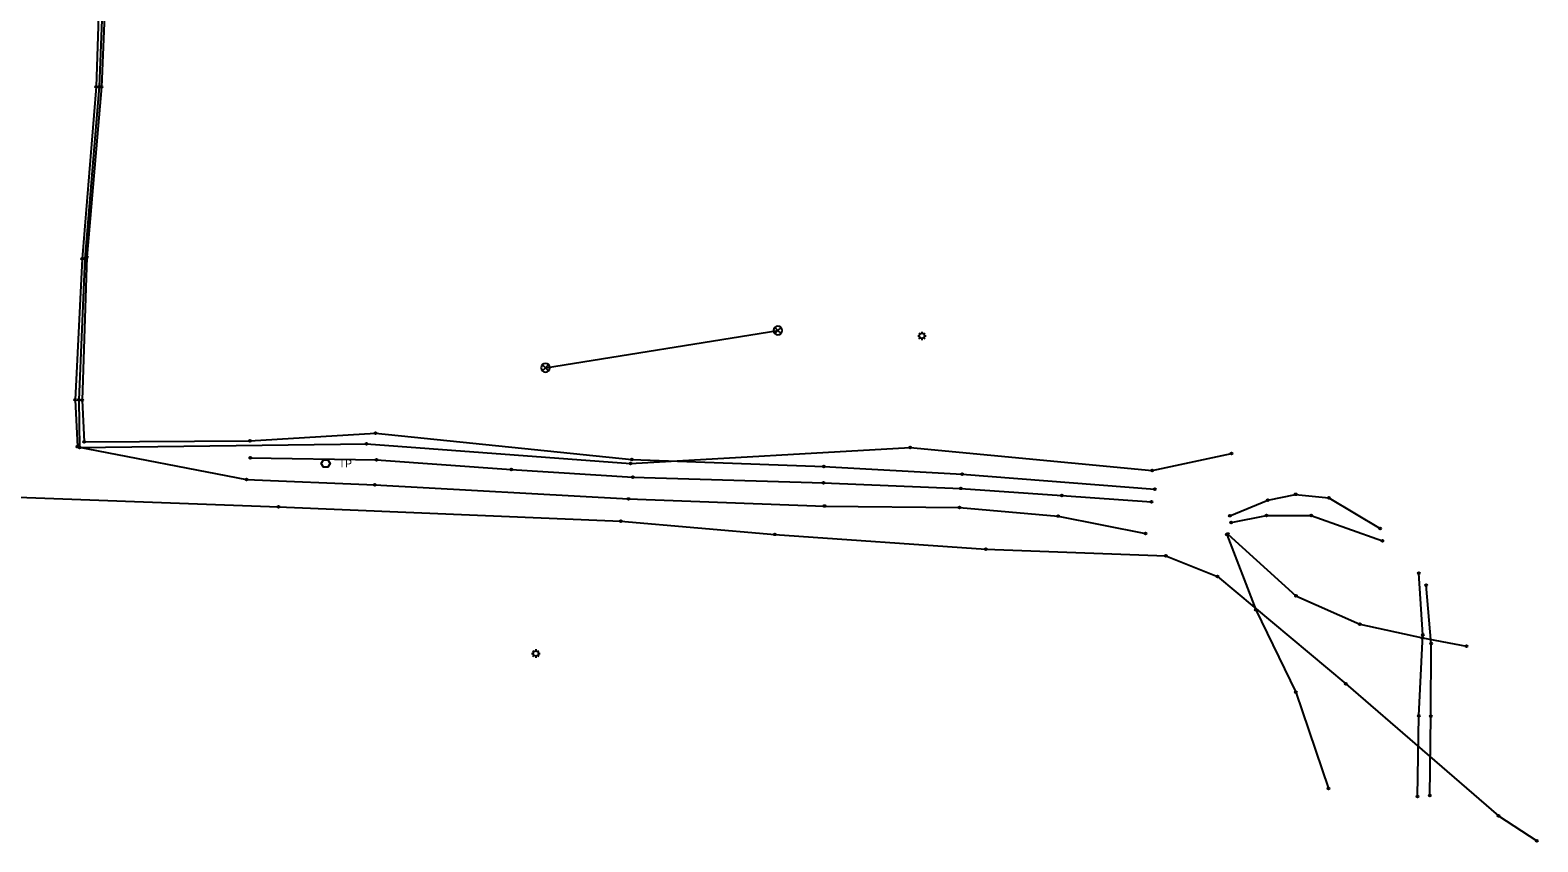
# Model space of a CAD drawing. Extents: x 20500343 to 20505311, y 7953484 to 7954193.
# Drawn here: x 20504997.9 to 20505310.5, y 7953483.9 to 7953652.3 of the extents above; entities that cross this region are included whole.
import ezdxf

# ---------------------------------------------------------------- set-up
doc = ezdxf.new("R2010")
doc.units = 0
for name, color, linetype in [('C-PROP-LINE-LOT', 7, 'Continuous'), ('V-ANNO-NOTE', 7, 'Continuous'), ('V-CTRL-HVPT', 7, 'Continuous'), ('V-SITE-FENC', 7, 'Continuous'), ('V-SSWR-STRC', 7, 'Continuous')]:
    doc.layers.add(name, color=color, linetype=linetype)

msp = doc.modelspace()

# ---------------------------------------------------------------- linework, layer by layer
at = {"layer": 'C-PROP-LINE-LOT'}
for points in [[(20505013.33, 7953703.56), (20505012.96, 7953693.72), (20505012.56, 7953669.99), (20505011.56, 7953640.51), (20505008.67, 7953604.85), (20505007.2, 7953575.58), (20505007.69, 7953565.88), (20505042.73, 7953559.05), (20505069.33, 7953557.97), (20505121.95, 7953555.03), (20505162.59, 7953553.57), (20505190.61, 7953553.26), (20505211.07, 7953551.49), (20505229.15, 7953547.86)], [(20505014.04, 7953703.48), (20505013.59, 7953693.59), (20505013.35, 7953670.1), (20505012.2, 7953640.55), (20505009.2, 7953604.9), (20505007.97, 7953575.58), (20505008.15, 7953565.68), (20505067.6, 7953566.47), (20505122.4, 7953562.4), (20505180.36, 7953565.69), (20505230.56, 7953560.95), (20505246.98, 7953564.46)], [(20505014.82, 7953703.33), (20505014.33, 7953693.64), (20505013.94, 7953670.31), (20505012.67, 7953640.54), (20505009.65, 7953605.21), (20505008.65, 7953575.55), (20505009.1, 7953566.88), (20505043.47, 7953567.1), (20505069.5, 7953568.67), (20505122.66, 7953563.23), (20505162.48, 7953561.76), (20505191.13, 7953560.15), (20505231.08, 7953557.04)], [(20504269.22, 7953602.59), (20504316.87, 7953595.9), (20504390.54, 7953591.68), (20504433.07, 7953588.04), (20504524.61, 7953579.67), (20504571.19, 7953575.9), (20504651.75, 7953571.77), (20504777.78, 7953566.7), (20504848.38, 7953562.34), (20504918.92, 7953559.08), (20504984.04, 7953555.83), (20505049.37, 7953553.38), (20505120.36, 7953550.4), (20505152.31, 7953547.69), (20505196.06, 7953544.59), (20505233.38, 7953543.22), (20505244.11, 7953538.95), (20505270.71, 7953516.66), (20505302.37, 7953489.32), (20505310.32, 7953484.09)], [(20505104.73, 7953582.26), (20505152.95, 7953589.98)], [(20505043.54, 7953563.54), (20505069.71, 7953563.13), (20505097.66, 7953561.13), (20505122.85, 7953559.53), (20505162.42, 7953558.4), (20505190.86, 7953557.23), (20505211.83, 7953555.73), (20505230.43, 7953554.42)], [(20505246.63, 7953551.56), (20505254.5, 7953554.8), (20505260.3, 7953555.99), (20505267.21, 7953555.26), (20505277.82, 7953548.89)], [(20505246.93, 7953550.16), (20505254.28, 7953551.61), (20505263.54, 7953551.61), (20505278.28, 7953546.35)], [(20505246, 7953547.69), (20505252.05, 7953532.06), (20505260.32, 7953514.97), (20505267.1, 7953494.97)], [(20505246.22, 7953547.76), (20505260.37, 7953534.96), (20505273.61, 7953529.08), (20505286.57, 7953526.24), (20505295.7, 7953524.51)], [(20505285.57, 7953493.31), (20505285.85, 7953510.07), (20505286.68, 7953526.84), (20505285.86, 7953539.66)], [(20505288.12, 7953493.5), (20505288.34, 7953509.99), (20505288.38, 7953525.07), (20505287.35, 7953537.15)]]:
    msp.add_lwpolyline(points, dxfattribs=at)
at = {"layer": 'V-ANNO-NOTE'}
for centre in [(20505011.56, 7953640.51), (20505012.2, 7953640.55), (20505012.67, 7953640.54), (20505009.65, 7953605.21), (20505008.67, 7953604.85), (20505009.2, 7953604.9), (20505007.2, 7953575.58), (20505007.97, 7953575.58), (20505008.65, 7953575.55), (20505069.5, 7953568.67), (20505007.69, 7953565.88), (20505008.15, 7953565.68), (20505009.1, 7953566.88), (20505043.47, 7953567.1), (20505067.6, 7953566.47), (20505180.36, 7953565.69), (20505246.98, 7953564.46), (20505043.54, 7953563.54), (20505069.71, 7953563.13), (20505122.4, 7953562.4), (20505122.66, 7953563.23), (20505162.48, 7953561.76), (20505042.73, 7953559.05), (20505097.66, 7953561.13), (20505122.85, 7953559.53), (20505162.42, 7953558.4), (20505191.13, 7953560.15), (20505230.56, 7953560.95), (20505069.33, 7953557.97), (20505121.95, 7953555.03), (20505190.86, 7953557.23), (20505211.83, 7953555.73), (20505231.08, 7953557.04), (20505260.3, 7953555.99), (20505267.21, 7953555.26), (20505049.37, 7953553.38), (20505162.59, 7953553.57), (20505190.61, 7953553.26), (20505230.43, 7953554.42), (20505254.5, 7953554.8), (20505120.36, 7953550.4), (20505211.07, 7953551.49), (20505246.63, 7953551.56), (20505246.93, 7953550.16), (20505254.28, 7953551.61), (20505263.54, 7953551.61), (20505277.82, 7953548.89), (20505152.31, 7953547.69), (20505229.15, 7953547.86), (20505246, 7953547.69), (20505246.22, 7953547.76), (20505278.28, 7953546.35), (20505196.06, 7953544.59), (20505233.38, 7953543.22), (20505285.86, 7953539.66), (20505244.11, 7953538.95), (20505287.35, 7953537.15), (20505260.37, 7953534.96), (20505252.05, 7953532.06), (20505273.61, 7953529.08), (20505286.68, 7953526.84), (20505286.57, 7953526.24), (20505288.38, 7953525.07), (20505295.7, 7953524.51), (20505260.32, 7953514.97), (20505270.71, 7953516.66), (20505285.85, 7953510.07), (20505288.34, 7953509.99), (20505267.1, 7953494.97), (20505285.57, 7953493.31), (20505288.12, 7953493.5), (20505302.37, 7953489.32), (20505310.32, 7953484.09)]:
    msp.add_circle(centre, 0.2, dxfattribs=at)
at = {"layer": 'V-CTRL-HVPT'}
for p, q in [((20505182.8, 7953589.73), (20505182.8, 7953589.4)), ((20505181.93, 7953588.86), (20505182.26, 7953588.86)), ((20505182.19, 7953589.48), (20505182.42, 7953589.25)), ((20505182.19, 7953588.25), (20505182.42, 7953588.48)), ((20505182.8, 7953588.32), (20505182.8, 7953587.99)), ((20505183.18, 7953589.25), (20505183.41, 7953589.48)), ((20505183.18, 7953588.48), (20505183.41, 7953588.25)), ((20505183.34, 7953588.86), (20505183.67, 7953588.86)), ((20505102.74, 7953523.84), (20505102.74, 7953523.51)), ((20505101.87, 7953522.97), (20505102.2, 7953522.97)), ((20505102.13, 7953523.58), (20505102.36, 7953523.35)), ((20505102.13, 7953522.35), (20505102.36, 7953522.58)), ((20505102.74, 7953522.42), (20505102.74, 7953522.1)), ((20505103.12, 7953523.35), (20505103.35, 7953523.58)), ((20505103.12, 7953522.58), (20505103.35, 7953522.35)), ((20505103.28, 7953522.97), (20505103.61, 7953522.97))]:
    msp.add_line(p, q, dxfattribs=at)
for centre in [(20505182.8, 7953588.86), (20505102.74, 7953522.97)]:
    msp.add_circle(centre, 0.543, dxfattribs=at)
at = {"layer": 'V-SITE-FENC'}
msp.add_lwpolyline([(20505058.25, 7953562.39), (20505058.7, 7953563.18), (20505059.62, 7953563.18), (20505060.07, 7953562.39), (20505059.62, 7953561.6), (20505058.7, 7953561.6), (20505058.25, 7953562.39)], dxfattribs=at)
at = {"layer": 'V-SSWR-STRC'}
for points in [[(20505152.31, 7953589.34), (20505152.95, 7953589.98), (20505152.31, 7953590.61)], [(20505153.59, 7953590.61), (20505152.95, 7953589.98), (20505153.59, 7953589.34)], [(20505104.09, 7953581.63), (20505104.73, 7953582.26), (20505104.09, 7953582.9)], [(20505105.37, 7953582.9), (20505104.73, 7953582.26), (20505105.37, 7953581.63)]]:
    msp.add_lwpolyline(points, dxfattribs=at)
for centre, start, end in [((20505152.95, 7953589.98), 135, 225), ((20505152.95, 7953589.98), 45, 135), ((20505152.95, 7953589.98), 315, 45), ((20505152.95, 7953589.98), 225, 315), ((20505104.73, 7953582.26), 135, 225), ((20505104.73, 7953582.26), 45, 135), ((20505104.73, 7953582.26), 225, 315), ((20505104.73, 7953582.26), 315, 45)]:
    msp.add_arc(centre, 0.899, start, end, dxfattribs=at)

# ---------------------------------------------------------------- texts
at = {"layer": 'V-SITE-FENC'}
msp.add_text('TP', height=1.599, dxfattribs=at).set_placement((20505061.9, 7953561.59))

doc.saveas('drawing.dxf')
